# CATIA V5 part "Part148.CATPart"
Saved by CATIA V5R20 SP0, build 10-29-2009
Part number: FA 105700-3
Revision: ANY
Definition: UNKNOWN
Nomenclature: FA 105700-3
Source: Unknown
Bounding box of the stored display mesh (mm): x -2.687 to 2.687, y -2.475 to 2.475, z -2.5 to 2.5
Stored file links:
  C:\Users\Utente\Desktop\IO LAVORO\3D X SITO CF\CUMSA\3D files FA\FA 105706-20\Part148.CATPart

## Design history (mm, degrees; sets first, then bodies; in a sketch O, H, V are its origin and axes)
Body1 "Chaflán4" (main body)
  Solid1: solid without history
